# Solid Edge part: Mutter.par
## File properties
Sűrűség: 0,000 kg/m^3
Pontosság: 0,990
Author: ahadarics
Last saved by: ahadarics
Revision: 76
Username: ahadarics
Dokumentum tartalom típus: 0
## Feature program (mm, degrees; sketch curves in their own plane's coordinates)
base feature "unnamed BaseFeature 1"
thread "unnamed Thread 1"
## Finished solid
Body 1: solid body, 23 faces, 46 edges, 24 vertices.
  Faces by surface: cone 14, plane 8, cylinder 1
  Edges by curve: spline 24, circle 16, line 6
Bounding box of the edges (mm): 8.000 x 27.713 x 24.000, from (0, -13.8564, -12) to (8, 13.8564, 12).
Cylindrical faces by radius (mm): R7.188 x1
Conical faces (half-angle, radius in mm at the cone's reference point): 60 deg R7.5939 x2, 60 deg R12.9282 x12
Planar faces by outward normal: +x 1, +z 1, -x 1, -z 1, oblique 4
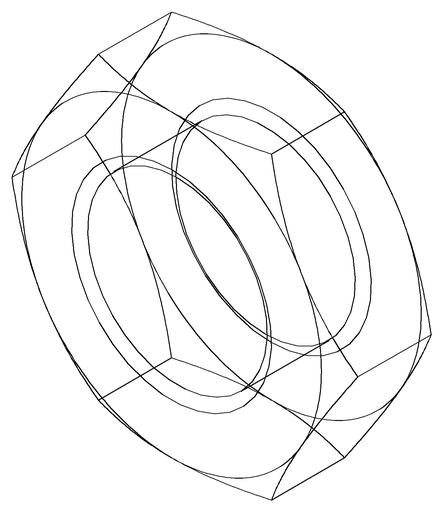
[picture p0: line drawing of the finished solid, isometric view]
